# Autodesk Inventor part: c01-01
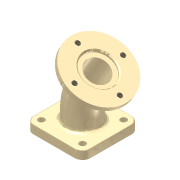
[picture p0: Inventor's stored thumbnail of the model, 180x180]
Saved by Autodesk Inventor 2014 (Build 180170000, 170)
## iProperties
Created: 2010-11
Part Number: c01-01
Material: Iron, Cast
Document SubType Name: Modeling
Designer: Thom Tremblay
Density: 7.25 g/cm^3
Mass: 1087.5 g
Surface Area: 260 cm^2
Volume: 150 cm^3
Appearance: Titanium - Polished
Author: Thom Tremblay
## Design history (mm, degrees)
sketch "Sketch1"
  geometry: L1 (-50, -50)-(50, -50); L2 (50, -50)-(50, 50); L3 (50, 50)-(-50, 50); L4 (-50, 50)-(-50, -50); C1 r 20 at (0, 0); C2 r 28 at (0, 0); 3 further points
  constraints: 8 end point, 3 perpendicular, 2 centre point, 2 coincident, 2 midpoint, 1 horizontal, 1 horizontal alignment, 1 parallel, 1 vertical alignment
  dimensions: "Width" = 100 distance of L1.start L1.end; "d6" = 40 diameter of C1; "d7" = 8 radial gap between concentric circles of C2 C1
extrude "Extrusion1" new body sketch "Sketch1" distance "d3" = 15; taper "d4" = 0 deg
fillet "Fillet1" dims "d5" = 14
sketch "Sketch2"
  geometry: L1 (0, 0)-(0, 30); L2 (-13.397, 80)-(-28.397, 105.981); A1 r 100 centre (-100, 30) between (0, 30) and (-13.397, 80)
  constraints: 4 end point, 2 point on circle, 2 tangent, 1 centre point, 1 vertical
  dimensions: "d8" = 30 distance of L1.start L1.end; "d9" = 100 radius of A1; "d10" = 30 distance of L2.start L2.end; "d11" = 30 deg angle of L2 L1
sketch "Sketch3"
  geometry: L1 (-13.397, 80)-(-28.397, 105.981) reference; L2 (-28.397, 105.981)-(-76.029, 78.481); L3 (-76.029, 78.481)-(-71.029, 69.821); L4 (-71.029, 69.821)-(-23.397, 97.321); L5 (-23.397, 97.321)-(-28.397, 105.981); 1 further point
  constraints: 8 end point, 2 parallel, 2 perpendicular
  dimensions: "d16" = 10 distance of L3.end L2.end; "d17" = 110 diameter of L3 L5
revolve "Revolution1" sketch "Sketch3" stored, may be unused: angle "d18" = 90 deg
sweep "Sweep1" dims "d19" = 0
sweep "Sweep2" dims "d20" = 0
sketch "Sketch4"
  geometry: C1 r 20 at (0, 0) reference; C2 r 55 at (0, 0) reference; C3 r 27.5 at (0, 0); 1 further point
  constraints: 1 centre point, 1 coincident
  dimensions: "d21" = 55 diameter of C3
extrude "Extrusion2" cut sketch "Sketch4" distance "d22" = 5; taper "d23" = 0 deg
sketch "Sketch5"
  geometry: L1 (0, 0)-(0, 9.711); L2 (-25, 0)-(-27, 0); L3 (-27, 0)-(-27, 1.5); L4 (-26.5, 2)-(-25.5, 2); L5 (-25, 1.5)-(-25, 0); A1 r 0.5 centre (-25.5, 1.5) between (-25, 1.5) and (-25.5, 2); A2 r 0.5 centre (-26.5, 1.5) between (-26.5, 2) and (-27, 1.5); 1 further point
  constraints: 10 end point, 4 point on circle, 4 tangent, 3 point on line, 2 centre point, 2 parallel, 1 equal radius, 1 horizontal, 1 perpendicular, 1 vertical
  dimensions: "d24" = 2 distance of L2.start L2.end; "d25" = 2 distance of point (-25, 2) L2.start; "d26" = 50 diameter of L5 L1; "d27" = 0.5 radius of A1
revolve "Revolution2" sketch "Sketch5" stored, may be unused: angle "d28" = 90 deg
hole "Hole1" diameter "d31" = 11; stored, may be unused: countersink angle "d35" = 7.5 deg, drill point angle "d37" = 118 deg; dims "d29" = 10, "d30" = 10, "d32" = 6, "d33" = 28, "d34" = 2, "d36" = 8
pattern_circular "Circular Pattern1" dims angle "d39" = 360 deg
sketch "Hole Sketch" dims "d41" = 85
  geometry: L1 (0, -42.5)-(-42.5, 0); L2 (-42.5, 0)-(0, 42.5); L3 (0, 42.5)-(42.5, 0); L4 (42.5, 0)-(0, -42.5); C1 r 27.5 at (0, 0) reference; 2 further points
  constraints: 8 end point, 2 coincident, 2 horizontal alignment, 11 other
hole "Hole2" sketch "Hole Sketch" at (0, -42.5), (-42.5, 0), (0, 42.5), (42.5, 0) diameter "d42" = 8.376; stored, may be unused: countersink angle "d46" = 90 deg, drill point angle "d48" = 118 deg; dims "d43" = 6, "d44" = 4, "d45" = 2, "d47" = 8
fillet "Fillet2" dims "d49" = 6, "d50" = 2, "d51" = 0.5
chamfer "Chamfer1" distance "d52" = 2; stored, may be unused: second distance "d53" = 2, angle "d54" = 45 deg
chamfer "Chamfer2" distance "d55" = 2; stored, may be unused: second distance "d56" = 4, angle "d57" = 45 deg
body "Solid1"
